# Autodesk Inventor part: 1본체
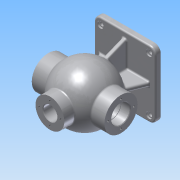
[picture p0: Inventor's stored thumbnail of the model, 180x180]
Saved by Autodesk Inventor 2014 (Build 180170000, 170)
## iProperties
Created: 2017-01
Part Number: 1본체
Material: Aluminum 6061
Document SubType Name: Modeling
Designer: ksu
Density: 2.71 g/cm^3
Appearance: Aluminum - Flat
Mass: 1515.97 g
Surface Area: 1159.86 cm^2
Volume: 559.398 cm^3
Author: ksu
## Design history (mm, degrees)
sketch "Sketch1"
  geometry: L1 (-45.5, -62.5)-(45.5, -62.5); L2 (57.5, -50.5)-(57.5, 50.5); L3 (45.5, 62.5)-(-45.5, 62.5); L4 (-57.5, 50.5)-(-57.5, -50.5); L5 (-57.5, -62.5)-(57.5, 62.5); L6 (57.5, -62.5)-(-57.5, 62.5); A1 r 12 centre (-45.5, 50.5) between (-45.5, 62.5) and (-57.5, 50.5); A2 r 12 centre (45.5, 50.5) between (57.5, 50.5) and (45.5, 62.5); A3 r 12 centre (45.5, -50.5) between (45.5, -62.5) and (57.5, -50.5); A4 r 12 centre (-45.5, -50.5) between (-57.5, -50.5) and (-45.5, -62.5); 1 further point
  constraints: 12 end point, 8 point on circle, 8 point on line, 8 tangent, 4 centre point, 3 equal radius, 2 midpoint, 2 parallel, 1 horizontal, 1 perpendicular
  dimensions: "d0" = 115 distance of L6.end L5.end; "d1" = 125 distance of L5.end L6.start; "d2" = 12 radius of A1
extrude "Extrusion1" new body sketch "Sketch1" distance "d3" = 10; taper "d4" = 0 deg
sketch "Sketch2"
  geometry: A1 r 12 centre (-45.5, 50.5) between (-45.5, 62.5) and (-57.5, 50.5) reference; A2 r 12 centre (-45.5, -50.5) between (-57.5, -50.5) and (-45.5, -62.5) reference; A3 r 12 centre (45.5, -50.5) between (45.5, -62.5) and (57.5, -50.5) reference; A4 r 12 centre (45.5, 50.5) between (57.5, 50.5) and (45.5, 62.5) reference; 5 further points
  constraints: 4 coincident
hole "Hole1" sketch "Sketch2" at (-45.5, 50.5), (-45.5, -50.5), (45.5, -50.5), (45.5, 50.5) diameter "d5" = 8; stored, may be unused: countersink angle "d9" = 90 deg, drill point angle "d11" = 118 deg; dims "d6" = 6, "d7" = 12, "d8" = 3, "d10" = 10
sketch "Sketch3"
  geometry: L1 (62.5, 10)-(62.5, 0) reference; L2 (62.5, 0)-(-62.5, 0) reference; L3 (-62.5, 0)-(-62.5, 10) reference; L4 (-62.5, 10)-(62.5, 10) reference; L5 (0, 138)-(0, 32); A1 r 53 centre (0, 85) between (0, 138) and (0, 32); 1 further point
  constraints: 2 end point, 2 point on circle, 1 centre point, 1 perpendicular
  dimensions: "d13" = 106 diameter of A1
revolve "Revolution1" sketch "Sketch3" stored, may be unused: angle "d14" = 90 deg
workplane "Work Plane1"
sketch "Sketch4"
  geometry: C1 r 27 at (0, 0); 1 further point
  constraints: 1 centre point, 1 coincident
  dimensions: "d16" = 54 diameter of C1
extrude "Extrusion2" join sketch "Sketch4" distance "d17" = 50; taper "d18" = 0 deg
sketch "Sketch5"
  geometry: C1 r 13 at (0, 0); 1 further point
  constraints: 1 centre point, 1 coincident
  dimensions: "d19" = 26 diameter of C1
extrude "Extrusion3" cut sketch "Sketch5" distance "d20" = 50; taper "d21" = 0 deg
sketch "Sketch6"
  geometry: L1 (62.5, 10)-(62.5, 0) reference; L2 (62.5, 0)-(-62.5, 0) reference; L3 (-62.5, 0)-(-62.5, 10) reference; L4 (-62.5, 10)-(62.5, 10) reference; L5 (-27, 130.607)-(-27, 150) reference; L6 (-27, 150)-(-13, 150) reference; L7 (-13, 150)-(-13, 100) reference; L8 (-13, 100)-(13, 100) reference; L9 (13, 100)-(13, 150) reference; L10 (13, 150)-(27, 150) reference; L11 (27, 150)-(27, 130.607) reference; C1 r 31 at (0, 85); A1 r 53 centre (0, 85) between (-27, 130.607) and (0, 32) reference; A2 r 53 centre (0, 85) between (0, 32) and (27, 130.607) reference; 1 further point
  constraints: 1 centre point, 1 coincident
  dimensions: "d22" = 62 diameter of C1
extrude "Extrusion4" join sketch "Sketch6" stored distance "d23" = 136; taper "d24" = 0 deg
sketch "Sketch7"
  geometry: C1 r 31 at (0, 0) reference; C2 r 17.5 at (0, 0); 1 further point
  constraints: 1 centre point, 1 coincident
  dimensions: "d25" = 35 diameter of C2
extrude "Extrusion5" cut sketch "Sketch7" stored distance "d26" = 136; taper "d27" = 0 deg
sketch "Sketch8"
  geometry: C1 r 31 at (0, 0) reference; A1 r 22.5 centre (0, 0) between (22.5, 0) and (0, -22.5); 3 further points
  constraints: 4 point on circle, 1 centre point, 1 coincident
  dimensions: "d28" = 45 diameter of A1
hole "Hole2" sketch "Sketch8" at (22.5, 0), (0, -22.5), (-22.5, 0), (0, 22.5) diameter "d29" = 3.459; stored, may be unused: countersink angle "d33" = 90 deg, drill point angle "d35" = 118 deg; dims "d30" = 12, "d31" = 12, "d32" = 3, "d34" = 15
sketch "Sketch9"
  geometry: C1 r 31 at (0, 0) reference; A1 r 24 centre (0, 0) between (0, 24) and (24, 0); 3 further points
  constraints: 4 point on circle, 1 centre point, 1 coincident
  dimensions: "d36" = 48 diameter of A1
hole "Hole3" sketch "Sketch9" at (0, 24), (24, 0), (0, -24), (-24, 0) diameter "d37" = 3.459; stored, may be unused: countersink angle "d41" = 90 deg, drill point angle "d43" = 118 deg; dims "d38" = 16, "d39" = 12, "d40" = 3, "d42" = 19
sketch "Sketch10"
  geometry: L1 (57.5, 10)-(57.5, 0) reference; L2 (57.5, 0)-(-57.5, 0) reference; L3 (-57.5, 0)-(-57.5, 10) reference; L4 (-57.5, 10)-(57.5, 10) reference; L5 (-42.988, 54)-(-68, 54) reference; L6 (-68, 54)-(-68, 59.27) reference; L7 (-68, 59.27)-(-49, 59.27) reference; L8 (-49, 59.27)-(-47.961, 61) reference; L9 (-47.961, 61)-(-49, 62.73) reference; L10 (-49, 62.73)-(-68, 62.73) reference; L11 (-68, 62.73)-(-68, 67.5) reference; L12 (-68, 67.5)-(68, 67.5) reference; L13 (68, 67.5)-(68, 64.23) reference; L14 (68, 64.23)-(53, 64.23) reference; L15 (53, 64.23)-(51.961, 62.5) reference; L16 (51.961, 62.5)-(53, 60.77) reference; L17 (53, 60.77)-(68, 60.77) reference; L18 (68, 60.77)-(68, 54) reference; L19 (68, 54)-(42.988, 54) reference; L20 (-27, 130.607)-(-27, 150) reference; L21 (-27, 150)-(-13, 150) reference; L22 (-13, 150)-(-13, 116) reference; L23 (-13, 116)-(13, 116) reference; L24 (13, 116)-(13, 150) reference; L25 (13, 150)-(27, 150) reference; L26 (27, 150)-(27, 130.607) reference; L27 (42.988, 116)-(68, 116) reference; L28 (68, 116)-(68, 109.23) reference; L29 (68, 109.23)-(53, 109.23) reference; L30 (53, 109.23)-(51.961, 107.5) reference; L31 (51.961, 107.5)-(53, 105.77) reference; L32 (53, 105.77)-(68, 105.77) reference; L33 (68, 105.77)-(68, 102.5) reference; L34 (68, 102.5)-(-68, 102.5) reference; L35 (-68, 102.5)-(-68, 107.27) reference; L36 (-68, 107.27)-(-49, 107.27) reference; L37 (-49, 107.27)-(-47.961, 109) reference; L38 (-47.961, 109)-(-49, 110.73) reference; L39 (-49, 110.73)-(-68, 110.73) reference; L40 (-68, 110.73)-(-68, 116) reference; L41 (-68, 116)-(-42.988, 116) reference; L42 (47.5, 10)-(27.723, 58.949); L43 (27.723, 58.949)-(0, 58.949); L44 (47.5, 10)-(0, 10); L45 (-27.723, 58.949)-(0, 58.949); L46 (0, 10)-(-47.5, 10); L47 (0, 58.949)-(0, 10); L48 (-47.5, 10)-(-27.723, 58.949); A1 r 53 centre (0, 85) between (-42.988, 54) and (0, 32) reference; A2 r 53 centre (0, 85) between (0, 32) and (42.988, 54) reference; A3 r 53 centre (0, 85) between (42.988, 116) and (27, 130.607) reference; A4 r 53 centre (0, 85) between (-27, 130.607) and (-42.988, 116) reference; 2 further points
  constraints: 14 end point, 2 symmetric about line, 1 collinear, 1 midpoint, 1 perpendicular, 1 point on circle
  dimensions: "d46" = 22 deg angle of L1 L42
extrude "Extrusion6" join sketch "Sketch10" stored distance "d47" = 8; taper "d48" = 0 deg
sketch "Sketch11"
  geometry: L1 (62.5, 10)-(62.5, 0) reference; L2 (62.5, 0)-(-62.5, 0) reference; L3 (-62.5, 0)-(-62.5, 10) reference; L4 (-62.5, 10)-(-4, 10) reference; L5 (-27, 130.607)-(-27, 150) reference; L6 (-27, 150)-(-13, 150) reference; L7 (-13, 150)-(-13, 113.142) reference; L8 (13, 113.142)-(13, 150) reference; L9 (13, 150)-(27, 150) reference; L10 (27, 150)-(27, 130.607) reference; L11 (4, 10)-(62.5, 10) reference; L12 (-52.5, 10)-(-36.349, 49.976); L13 (-36.349, 49.976)-(0, 49.976); L14 (0, 49.976)-(0, 0); L15 (36.349, 49.976)-(0, 49.976); L16 (52.5, 10)-(36.349, 49.976); L17 (-52.5, 10)-(52.5, 10); L18 (-4, 10)-(4, 10) reference; L19 (-4, 10)-(-4, 32.151) reference; L20 (4, 32.151)-(4, 10) reference; C1 r 17.5 at (0, 85) reference; A1 r 53 centre (0, 85) between (-27, 130.607) and (-4, 32.151) reference; A2 r 31 centre (0, 85) between (13, 113.142) and (-13, 113.142) reference; A3 r 53 centre (0, 85) between (4, 32.151) and (27, 130.607) reference; A4 r 53 centre (0, 85) between (-4, 32.151) and (4, 32.151) reference
  constraints: 12 end point, 2 symmetric about line, 1 collinear, 1 parallel, 1 perpendicular, 1 point on line
  dimensions: "d49" = 10 distance from line of L12.start L3; "d50" = 22 deg angle of L3 L12
extrude "Extrusion7" join sketch "Sketch11" stored distance "d51" = 8; taper "d52" = 0 deg
sketch "Sketch12"
  geometry: L1 (-68, 116)-(-42.988, 116) reference; L2 (-68, 54)-(-68, 59.27) reference; L3 (-68, 59.27)-(-49, 59.27) reference; L4 (-49, 59.27)-(-47.961, 61) reference; L5 (-47.961, 61)-(-49, 62.73) reference; L6 (-49, 62.73)-(-68, 62.73) reference; L7 (-68, 62.73)-(-68, 67.5) reference; L8 (-68, 67.5)-(68, 67.5) reference; L9 (68, 67.5)-(68, 64.23) reference; L10 (68, 64.23)-(53, 64.23) reference; L11 (53, 64.23)-(51.961, 62.5) reference; L12 (51.961, 62.5)-(53, 60.77) reference; L13 (53, 60.77)-(68, 60.77) reference; L14 (68, 60.77)-(68, 54) reference; L15 (42.988, 116)-(68, 116) reference; L16 (4, 10)-(57.5, 10) reference; L17 (57.5, 10)-(57.5, 0) reference; L18 (57.5, 0)-(-57.5, 0) reference; L19 (-57.5, 0)-(-57.5, 10) reference; L20 (-57.5, 10)-(-47.5, 10) reference; L21 (-27, 130.607)-(-27, 150) reference; L22 (-27, 150)-(-13, 150) reference; L23 (-13, 150)-(-13, 116) reference; L24 (-13, 116)-(13, 116) reference; L25 (13, 116)-(13, 150) reference; L26 (13, 150)-(27, 150) reference; L27 (27, 150)-(27, 130.607) reference; L28 (68, 54)-(42.988, 54) reference; L29 (68, 116)-(68, 109.23) reference; L30 (68, 109.23)-(53, 109.23) reference; L31 (53, 109.23)-(51.961, 107.5) reference; L32 (51.961, 107.5)-(53, 105.77) reference; L33 (53, 105.77)-(68, 105.77) reference; L34 (68, 105.77)-(68, 102.5) reference; L35 (68, 102.5)-(-68, 102.5) reference; L36 (-68, 102.5)-(-68, 107.27) reference; L37 (-68, 107.27)-(-49, 107.27) reference; L38 (-49, 107.27)-(-47.961, 109) reference; L39 (-47.961, 109)-(-49, 110.73) reference; L40 (-49, 110.73)-(-68, 110.73) reference; L41 (-68, 110.73)-(-68, 116) reference; L42 (-42.988, 54)-(-68, 54) reference; L43 (0, 128)-(0, 42); L44 (-47.5, 10)-(-33.719, 44.109) reference; L45 (4, 32.151)-(4, 10) reference; A1 r 53 centre (0, 85) between (42.988, 116) and (27, 130.607) reference; A2 r 53 centre (0, 85) between (-27, 130.607) and (-42.988, 116) reference; A3 r 53 centre (0, 85) between (4, 32.151) and (42.988, 54) reference; A4 r 53 centre (0, 85) between (-42.988, 54) and (-33.719, 44.109) reference; A5 r 43 centre (0, 85) between (0, 128) and (0, 42); 1 further point
  constraints: 2 end point, 2 point on circle, 1 centre point, 1 coincident, 1 perpendicular
revolve "Revolution2" sketch "Sketch12" stored, may be unused: angle "d54" = 90 deg
sketch "Sketch13"
  geometry: L1 (-68, 116)-(-42.988, 116) reference; L2 (-68, 54)-(-68, 59.27) reference; L3 (-68, 59.27)-(-49, 59.27) reference; L4 (-49, 59.27)-(-47.961, 61) reference; L5 (-47.961, 61)-(-49, 62.73) reference; L6 (-49, 62.73)-(-68, 62.73) reference; L7 (-68, 62.73)-(-68, 67.5) reference; L8 (-68, 67.5)-(-39.278, 67.5) reference; L9 (39.278, 67.5)-(68, 67.5) reference; L10 (68, 67.5)-(68, 64.23) reference; L11 (68, 64.23)-(53, 64.23) reference; L12 (53, 64.23)-(51.961, 62.5) reference; L13 (51.961, 62.5)-(53, 60.77) reference; L14 (53, 60.77)-(68, 60.77) reference; L15 (68, 60.77)-(68, 54) reference; L16 (42.988, 116)-(68, 116) reference; L17 (4, 10)-(57.5, 10) reference; L18 (57.5, 10)-(57.5, 0) reference; L19 (57.5, 0)-(-57.5, 0) reference; L20 (-57.5, 0)-(-57.5, 10) reference; L21 (-57.5, 10)-(-47.5, 10) reference; L22 (27, 150)-(27, 130.607) reference; L23 (68, 54)-(42.988, 54) reference; L24 (68, 116)-(68, 109.23) reference; L25 (68, 109.23)-(53, 109.23) reference; L26 (53, 109.23)-(51.961, 107.5) reference; L27 (51.961, 107.5)-(53, 105.77) reference; L28 (53, 105.77)-(68, 105.77) reference; L29 (68, 105.77)-(68, 102.5) reference; L30 (68, 102.5)-(39.278, 102.5) reference; L31 (13, 125.988)-(13, 150) reference; L32 (13, 150)-(27, 150) reference; L33 (-27, 130.607)-(-27, 150) reference; L34 (-27, 150)-(-13, 150) reference; L35 (-13, 150)-(-13, 125.988) reference; L36 (-39.278, 102.5)-(-68, 102.5) reference; L37 (-68, 102.5)-(-68, 107.27) reference; L38 (-68, 107.27)-(-49, 107.27) reference; L39 (-49, 107.27)-(-47.961, 109) reference; L40 (-47.961, 109)-(-49, 110.73) reference; L41 (-49, 110.73)-(-68, 110.73) reference; L42 (-68, 110.73)-(-68, 116) reference; L43 (-42.988, 54)-(-68, 54) reference; L44 (-68, 102.5)-(-68, 67.5); L45 (-52, 85)-(-50.25, 85); L46 (-52, 85)-(-50.25, 85); L47 (-50.25, 85)-(-50.25, 103.5); L48 (-50.25, 103.5)-(-52, 103.5); L49 (-52, 103.5)-(-52, 85); L50 (-47.5, 10)-(-33.719, 44.109) reference; L51 (4, 32.151)-(4, 10) reference; A1 r 43 centre (0, 85) between (-39.278, 67.5) and (0, 42) reference; A2 r 43 centre (0, 85) between (0, 42) and (39.278, 67.5) reference; A3 r 53 centre (0, 85) between (42.988, 116) and (27, 130.607) reference; A4 r 53 centre (0, 85) between (-27, 130.607) and (-42.988, 116) reference; A5 r 53 centre (0, 85) between (4, 32.151) and (42.988, 54) reference; A6 r 43 centre (0, 85) between (39.278, 102.5) and (13, 125.988) reference; A7 r 43 centre (0, 85) between (-13, 125.988) and (-39.278, 102.5) reference; A8 r 53 centre (0, 85) between (-42.988, 54) and (-33.719, 44.109) reference; 1 further point
  constraints: 12 end point, 2 parallel, 2 perpendicular, 1 horizontal
  dimensions: "d56" = 1.75 distance of L48.end L47.end; "d57" = 18.5 distance of L45.end L47.end
revolve "Revolution3" sketch "Sketch13" stored, may be unused: angle "d58" = 90 deg
sketch "Sketch14"
  geometry: C1 r 27 at (0, 0) reference; A1 r 20 centre (0, 0) between (0, 20) and (-20, 0); 2 further points
  constraints: 4 point on circle, 1 centre point, 1 coincident
  dimensions: "d59" = 40 diameter of A1
hole "Hole4" sketch "Sketch14" at (0, 20), (-20, 0), (20, 0), (0, -20) diameter "d60" = 3.459; stored, may be unused: countersink angle "d64" = 90 deg, drill point angle "d66" = 118 deg; dims "d61" = 9, "d62" = 12, "d63" = 3, "d65" = 11
workplane "Work Plane2"
sketch "Sketch15"
  geometry: L1 (-27, 150)-(27, 150) reference; L2 (-27, 150)-(-27, 130.607) reference; L3 (27, 150)-(27, 130.607) reference; L4 (-27, 130.607)-(27, 130.607) reference; L5 (-20.739, 143.002)-(20.739, 143.002); L6 (20.739, 143.002)-(20.739, 136.998); L7 (20.739, 136.998)-(-20.739, 136.998); L8 (-20.739, 136.998)-(-20.739, 143.002); 1 further point
  constraints: 2 other
emboss "Emboss1" sketch "Sketch15" dims "d0" = 115, "d1" = 125, "d2" = 12, "d70" = 0.5, "d71" = 0
fillet "Fillet1" dims "d72" = 3
chamfer "Chamfer1" distance "d73" = 1; stored, may be unused: second distance "d74" = 2, angle "d75" = 45 deg
fillet "Fillet2" dims "d76" = 3
fillet "Fillet3" dims "d77" = 3
chamfer "Chamfer2" distance "d78" = 1; stored, may be unused: second distance "d79" = 2, angle "d80" = 45 deg
mirror "Mirror1"
fillet "Fillet4" dims "d82" = 3
fillet "Fillet5" dims "d83" = 3
body "Solid1"
node "Project Cut Edges1"
node "Project Cut Edges2"
node "Project Cut Edges3"
node "Project Cut Edges4"
node "Project Cut Edges5"
node "Project Cut Edges6"
other parameters: "d53" = 86, "d67" = -27
